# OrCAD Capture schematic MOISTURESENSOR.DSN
size A; title: Moisture Sensor circuit; rev: 1
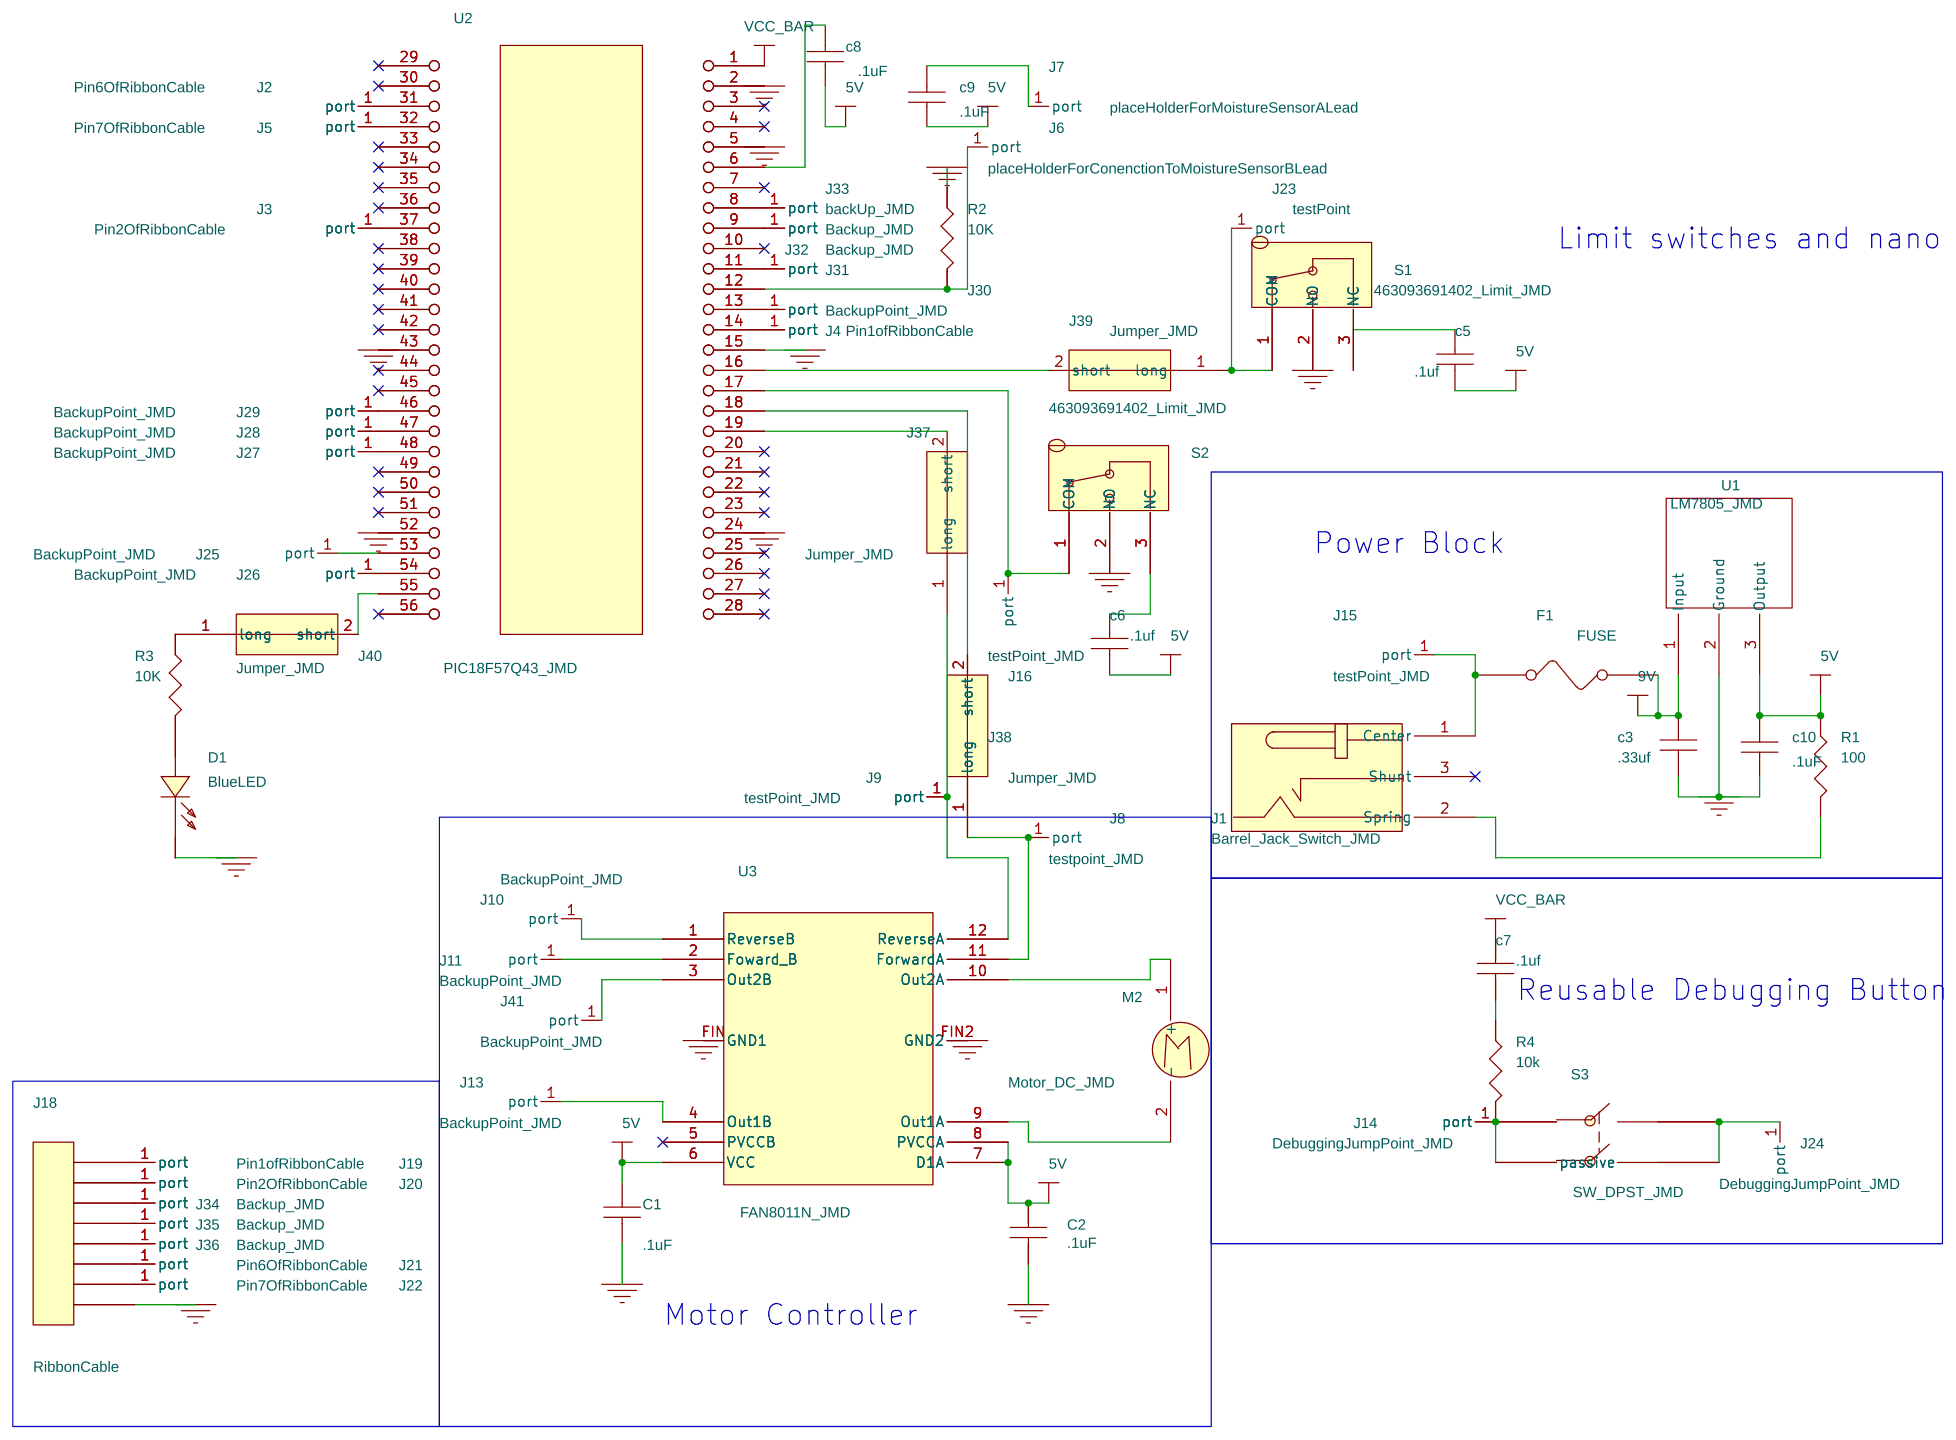
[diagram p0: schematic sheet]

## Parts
C1  .1uF  [capacitor]
C2  .1uF  [capacitor]
c3  .33uf  [capacitor]
c5  .1uf  [capacitor]
c6  .1uf  [capacitor]
c7  .1uf  [capacitor]
c8  .1uF  [capacitor]
c9  .1uF  [capacitor]
c10  .1uF  [capacitor]
D1  BlueLED  [capacitor]
F1  FUSE
J1  Barrel_Jack_Switch_JMD  [BarrelJackdevelopers_JMD]
J2  Pin6OfRibbonCable  [MalePinHole]
J3  Pin2OfRibbonCable  [MalePinHole]
J4  Pin1ofRibbonCable  [MalePinHole]
J5  Pin7OfRibbonCable  [MalePinHole]
J6  placeHolderForConenctionToMoistureSensorBLead  [MalePinHole]
J7  placeHolderForMoistureSensorALead  [MalePinHole]
J8  testpoint_JMD  [MalePinHole]
J9  testPoint_JMD  [MalePinHole]
J10  BackupPoint_JMD  [MalePinHole]
J11  BackupPoint_JMD  [MalePinHole]
J13  BackupPoint_JMD  [MalePinHole]
J14  DebuggingJumpPoint_JMD  [MalePinHole]
J15  testPoint_JMD  [MalePinHole]
J16  testPoint_JMD  [MalePinHole]
J18  RibbonCable
J19  Pin1ofRibbonCable  [MalePinHole]
J20  Pin2OfRibbonCable  [MalePinHole]
J21  Pin6OfRibbonCable  [MalePinHole]
J22  Pin7OfRibbonCable  [MalePinHole]
J23  testPoint  [MalePinHole]
J24  DebuggingJumpPoint_JMD  [MalePinHole]
J25  BackupPoint_JMD  [MalePinHole]
J26  BackupPoint_JMD  [MalePinHole]
J27  BackupPoint_JMD  [MalePinHole]
J28  BackupPoint_JMD  [MalePinHole]
J29  BackupPoint_JMD  [MalePinHole]
J30  BackupPoint_JMD  [MalePinHole]
J31  Backup_JMD  [MalePinHole]
J32  Backup_JMD  [MalePinHole]
J33  backUp_JMD  [MalePinHole]
J34  Backup_JMD  [MalePinHole]
J35  Backup_JMD  [MalePinHole]
J36  Backup_JMD  [MalePinHole]
J37  Jumper_JMD  [capacitor]
J38  Jumper_JMD  [capacitor]
J39  Jumper_JMD  [capacitor]
J40  Jumper_JMD  [capacitor]
J41  BackupPoint_JMD  [MalePinHole]
M2  Motor_DC_JMD  [screwTerminal]
R1  100  [Resistor_intro]
R2  10K  [Resistor_intro]
R3  10K  [Resistor_intro]
R4  10k  [Resistor_intro]
S1  463093691402_Limit_JMD  [463093691402_limitSwitch_JMD]
S2  463093691402_Limit_JMD  [463093691402_limitSwitch_JMD]
S3  SW_DPST_JMD  [sw_dpst]
U1  LM7805_JMD  [LinearVoltReg]
U2  PIC18F57Q43_JMD  [Microchip_PIC18F57Q43]
U3  FAN8011N_JMD  [hBridgeWithFin]

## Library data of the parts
C1 C2 c3 c5-c10 = CAPACITOR_NON-POL
D1 = LED
F1 = FUSE
J1 = Barrel_Jack_Switch_JMD
J2-J11 J14-J16 J19-J36 = MalePinPlaceHolder_JMD
J13 J41 = MalePinPlaceHolder_JMD_0
J18 = CONN_TRBLK_8
J37-J40 = MaleHeaderPin_JMD
M2 = Motor_DC_JMD
R1-R4 = RESISTOR
S1 S2 = 463093691402_Limit_JMD
S3 = SW_DPST_JMD
U1 = LM7805_JMD_0
U2 = PIC18F57Q43_JMD
U3 = FAN8011N_JMD

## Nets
5v: C1.1 C2.1 c5.2 c6.2 c7.1 c8.1 c9.1 c10.2 R1.1 U1.3(Output) U3.6(VCC) U3.7(D1A) U3.8(PVCCA)
9v: c3.1 F1.2 U1.1(Input)
+5V: U2.1(Vbus)
GND: C1.2 C2.2 c3.2 c10.1 R2.1 S1.2(NO) S2.2(NO) U1.2(Ground) U2.5(GND1) U2.15(GND2) U2.24(GND3) U2.52(GND5) U3.FIN(GND1) U3.FIN2(GND2)
GND_POWER: D1.1(CATHODE) J18.8 U2.2(VOFF) U2.43(GND4)
N10172: J1.2(Spring) R1.2
N11688: J8.1(port) J38.1(long) U3.11(ForwardA)
N11692: M2.1(+) U3.10(Out2A)
N11744: M2.2(-) U3.9(Out1A)
N12185: J37.2(short) U2.19(RB5)
N12217: J38.2(short) U2.18(RD5)
N12354: J16.1(port) S2.1(COM) U2.17(RD6)
N12502: c6.1 S2.3(NC)
N12545: J6.1(port) R2.2 U2.12(RA2)
N13111: F1.1 J1.1(Center) J15.1(port)
N13485: c5.1 S1.3(NC)
N13690: c9.2 J7.1(port)
N14820: J13.1(port) U3.4(Out1B)
N14829: J41.1(port) U3.3(Out2B)
N14838: J11.1(port) U3.2(Foward_B)
N14844: J10.1(port) U3.1(ReverseB)
N14994: J14.1(port) R4.2 S3.1(passive) S3.3
N14998: J24.1(port) S3.2 S3.4
N16476: c8.2 U2.6(VTG)
N17924: J23.1(port) J39.1(long) S1.1(COM)
N17960: J9.1(port) J37.1(long) U3.12(ReverseA)
N28673: J39.2(short) U2.16(RD7)
N29488: J40.2(short) U2.55(RF2)
N39935: J25.1(port) U2.53(RF0)
N43236: c7.2 R4.1
N43978: J18.6 J21.1(port)
N43979: J4.1(port) U2.14(RA0)
N43980: J30.1(port) U2.13(RA1)
N43983: J18.2 J20.1(port)
N43984: D1.2(ANODE) R3.2
N43985: J29.1(port) U2.46(RE2)
N43987: J18.4 J35.1(port)
N43988: J5.1(port) U2.32(RF1U)
N43990: J2.1(port) U2.31(RF0U)
N43991: J32.1(port) U2.9(RA5)
N43993: J27.1(port) U2.48(RD0)
N43994: J26.1(port) U2.54(RF1)
N43995: J33.1(port) U2.8(RA6)
N43998: J40.1(long) R3.1
N43999: J3.1(port) U2.37(RB2)
N44001: J18.7 J22.1(port)
N44002: J18.1 J19.1(port)
N44003: J28.1(port) U2.47(RC7)
N44005: J31.1(port) U2.11(RB0)
N44006: J18.3 J34.1(port)
N44007: J18.5 J36.1(port)

Not connected (* = marked no-connect by the designer): J1 3(Shunt)*; U2 3(RE3)* 4(RB7)* 7(RA7)* 10(RB3)* 20(RF7)* 21(RF6)* 22(RF5)* 23(RF4)* 25(RE1)* 26(RE0)* 27(RC1)* 28(RC0)* 29(NC)* 30(ID)* 33(RB6)* 34(RB4)* 35(RC2)* 36(RC3)* 38(RB1)* 39(RC4)* 40(RC5)* 41(RC6)* 42(RD4)* 44(RA3)* 45(RA4)* 49(RD1)* 50(RD2)* 51(RD3)* 56(RF3)*; U3 5(PVCCB)*

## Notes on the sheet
- Limit switches and nano
- Power Block
- Reusable Debugging Button
- Motor Controller
